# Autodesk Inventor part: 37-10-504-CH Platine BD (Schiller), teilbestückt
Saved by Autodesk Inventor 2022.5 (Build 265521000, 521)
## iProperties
Created: 2024-12
Part Number: 37-10-504-CH Platine BD (Schiller), teilbestückt
Material: Generic
Document SubType Name: Modeling
Designer: AdminForWorker
Density: 1 g/cm^3
Appearance: Default
Title: 37-10-504-CH Platine BD (Schiller), teilbestückt
Author: AdminForWorker
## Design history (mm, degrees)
feature "Body1"
body "Solid1"
